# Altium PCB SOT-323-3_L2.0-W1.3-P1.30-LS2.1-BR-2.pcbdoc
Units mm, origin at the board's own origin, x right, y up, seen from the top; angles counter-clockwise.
Board outline 15.62 x 14.95 mm, 2 copper layers (Top Layer, Bottom Layer), stack 0 mm thick; 1 components, 0 nets, 3 pads, 0 vias.
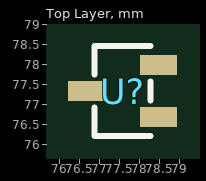
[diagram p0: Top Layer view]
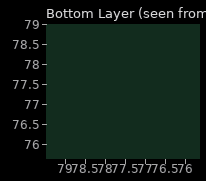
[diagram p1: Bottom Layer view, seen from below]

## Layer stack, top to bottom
Top Layer: signal copper (thickness not stored)
Bottom Layer: signal copper (thickness not stored)

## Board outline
85.466,69.85 69.85,69.85 69.85,84.802 85.466,84.802

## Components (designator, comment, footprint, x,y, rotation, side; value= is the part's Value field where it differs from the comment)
U? "" SOT-323-3_L2.0-W1.3-P1.30-LS2.1-BR-2 77.566,77.326 r0 top

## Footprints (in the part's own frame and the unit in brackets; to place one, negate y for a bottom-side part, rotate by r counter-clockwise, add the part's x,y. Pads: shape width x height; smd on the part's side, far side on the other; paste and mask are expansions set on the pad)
SOT-323-3_L2.0-W1.3-P1.30-LS2.1-BR-2 [mm]
  rect 0.936x0.5 smd: 1(0.898,-0.65) 2(0.898,0.65) 3(-0.898,0)
  silkscreen extent -0.7,-1.13 0.7,1.13

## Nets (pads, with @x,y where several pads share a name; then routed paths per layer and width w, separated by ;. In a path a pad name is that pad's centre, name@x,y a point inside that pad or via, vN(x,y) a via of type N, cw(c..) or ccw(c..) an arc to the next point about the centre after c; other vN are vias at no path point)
pads on no net: U?.1 U?.2 U?.3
